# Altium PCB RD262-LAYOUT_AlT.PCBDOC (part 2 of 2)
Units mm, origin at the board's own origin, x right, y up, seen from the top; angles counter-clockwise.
Board outline 110 x 64.13 mm, 4 copper layers (TOP, Mid-Layer 1, Mid-Layer 2, BOTTOM), stack 0.711 mm thick; 50 components, 28 nets, 252 pads, 303 vias.
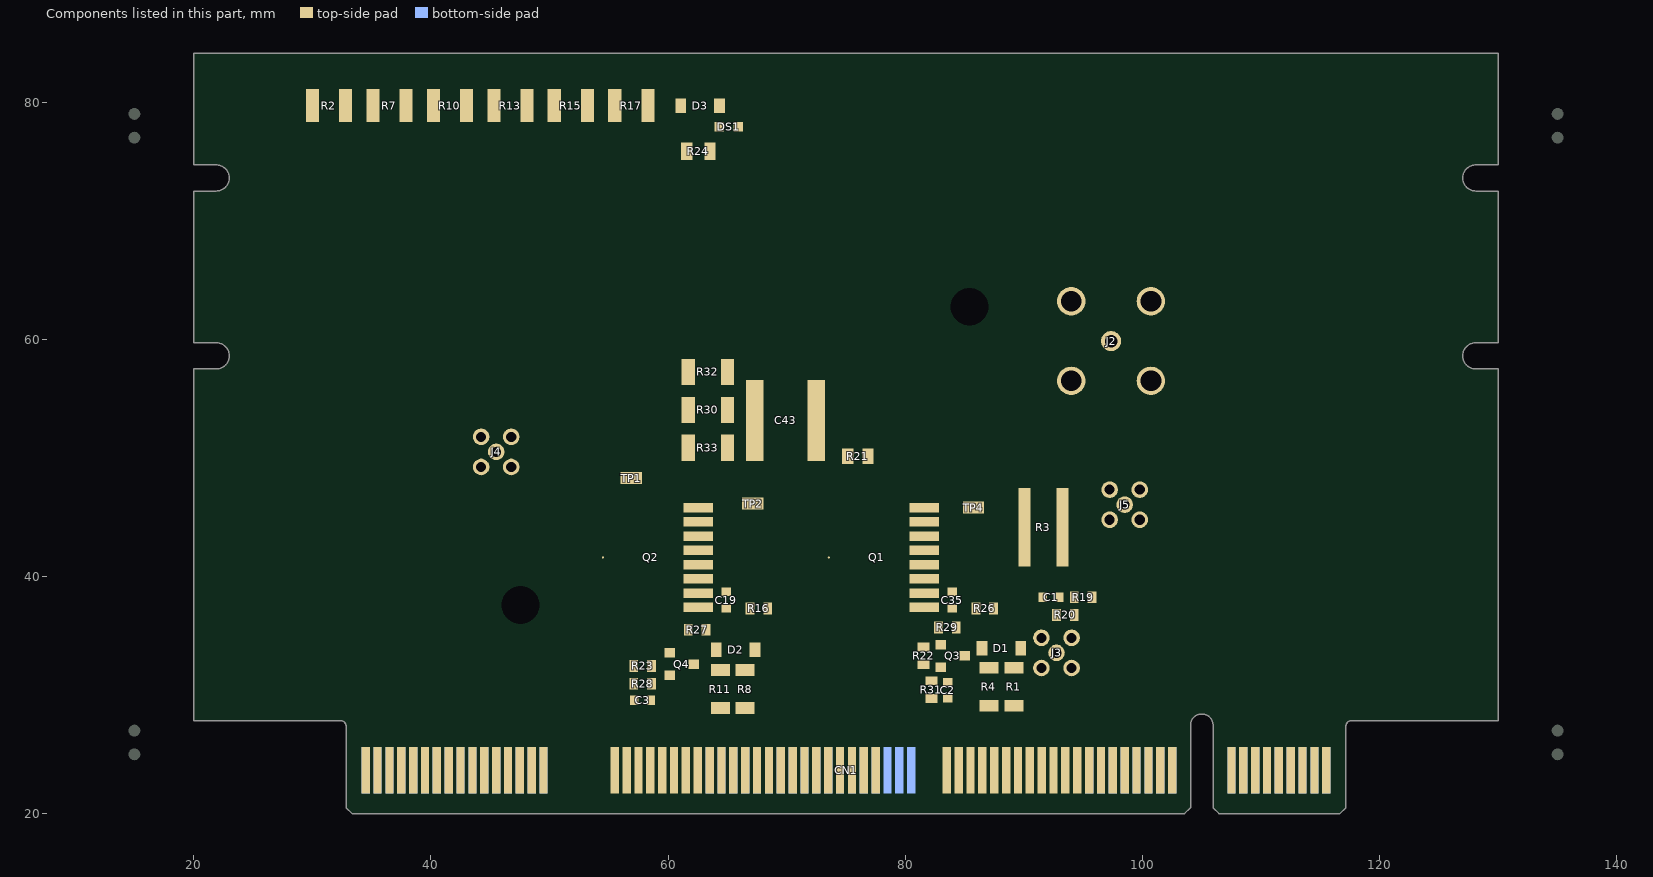
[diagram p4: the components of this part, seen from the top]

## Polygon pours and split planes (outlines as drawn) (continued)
N12552974 on Mid-Layer 2 "MID235" (solid, pour order 12): 34.2,21.7 cw(c34.2,21.75) 34.15,21.75 34.15,26 33.865,26.285 cw(c33.9,26.321) 33.85,26.321 33.85,29.35 32.85,30.35 25.521,30.35 cw(c25.521,30.4) 25.485,30.365 25.015,30.835 cw(c25.05,30.871) 25,30.871 25,81.079 cw(c25.05,81.079) 25.015,81.115 25.016,81.116 25.485,81.585 cw(c25.521,81.55) 25.521,81.6 121.529,81.6 cw(c121.529,81.55) 121.565,81.585 121.566,81.584 122.034,81.116 122.035,81.115 cw(c122,81.079) 122.05,81.079 122.05,30.871 cw(c122,30.871) 122.035,30.835 122.034,30.834 121.565,30.365 cw(c121.529,30.4) 121.529,30.35 117.15,30.35 116.15,29.35 116.15,26.321 cw(c116.1,26.321) 116.135,26.285 116.134,26.284 115.85,26 115.85,21.75 cw(c115.8,21.75) 115.8,21.7 107.2,21.7 cw(c107.2,21.75) 107.15,21.75 107.15,26 106.965,26.185 cw(c107,26.221) 106.95,26.221 106.95,27.45 ccw(c105,27.45) 103.05,27.45 103.05,26.221 cw(c103,26.221) 103.035,26.185 103.034,26.184 102.85,26 102.85,21.75 cw(c102.8,21.75) 102.8,21.7 95.2,21.7 cw(c95.2,21.75) 95.15,21.75 95.15,31.022 cw(c95.2,31.022) 95.166,31.058 ccw(c94.02,32.28) 95.695,32.28 95.695,37.4 cw(c95.745,37.4) 95.745,37.45 96.25,37.45 ccw(c96.25,38.95) 97.311,37.889 99.561,40.139 ccw(c98.5,41.2) 100,41.2 100,43.05 cw(c100.05,43.05) 100.049,43.1 ccw(c100.029,44.15) 100.771,43.407 100.772,43.408 101.142,43.778 ccw(c100.4,44.521) 101.45,44.521 101.45,47.579 ccw(c100.4,47.579) 101.142,48.322 100.772,48.692 ccw(c100.029,47.95) 100.029,49 96.971,49 ccw(c96.971,47.95) 96.228,48.692 96.15,48.615 cw(c96.115,48.65) 96.115,48.6 84.271,48.6 cw(c84.271,48.65) 84.235,48.615 83.765,49.085 cw(c83.8,49.121) 83.75,49.121 83.75,51.556 cw(c83.8,51.556) 83.766,51.592 83.808,51.634 83.809,51.634 90.225,58.05 cw(c90.26,58.015) 90.26,58.065 92.336,58.065 cw(c92.336,58.015) 92.373,57.981 ccw(c93.991,56.491) 93.951,54.292 93.952,54.292 ccw(c93.991,56.491) 95.61,57.981 cw(c95.647,58.015) 95.647,58.065 96.857,58.065 cw(c96.857,58.015) 96.87,58.063 ccw(c97.35,59.85) 96.87,61.637 cw(c96.857,61.685) 96.857,61.635 95.647,61.635 cw(c95.647,61.685) 95.61,61.719 ccw(c93.991,63.209) 93.952,65.408 93.951,65.408 ccw(c93.991,63.209) 92.373,61.719 cw(c92.336,61.685) 92.336,61.635 89.707,61.635 ccw(c89.707,59.35) 88.091,60.966 81.675,54.55 cw(c81.64,54.585) 81.64,54.535 74.707,54.535 ccw(c74.707,52.25) 73.092,53.866 73.091,53.866 71.736,52.51 71.735,52.51 71.728,52.502 ccw(c73.35,50.893) 71.065,50.893 71.065,49.5 cw(c71.015,49.5) 71.015,49.45 63.633,49.45 cw(c63.632,49.5) 63.587,49.478 ccw(c61.55,48.443) 63.166,50.059 61.609,51.616 61.599,51.625 61.599,51.626 ccw(c59.993,50) 59.993,52.285 48.4,52.285 cw(c48.4,52.335) 48.353,52.319 ccw(c46.77,51.77) 45.537,52.904 cw(c45.5,52.937) 45.463,52.904 ccw(c44.23,51.77) 43.096,50.537 cw(c43.063,50.5) 43.096,50.463 ccw(c44.23,49.23) 45.463,48.096 cw(c45.5,48.063) 45.537,48.096 ccw(c46.77,49.23) 48.353,48.681 cw(c48.4,48.665) 48.4,48.715 58.45,48.715 cw(c58.45,48.665) 58.5,48.665 58.5,36.6 cw(c58.45,36.6) 58.45,36.55 53.4,36.55 50.301,33.451 50.3,33.45 50.299,33.449 49.85,33 49.85,21.75 cw(c49.8,21.75) 49.8,21.7
0VA on Mid-Layer 2 "MID234" (solid, pour order 11): 96.971,44.1 cw(c96.971,44.15) 96.935,44.115 96.565,44.485 cw(c96.6,44.521) 96.55,44.521 96.55,47.579 cw(c96.6,47.579) 96.565,47.615 96.935,47.985 cw(c96.971,47.95) 96.971,48 100.029,48 cw(c100.029,47.95) 100.065,47.985 100.435,47.615 cw(c100.4,47.579) 100.45,47.579 100.45,44.521 cw(c100.4,44.521) 100.435,44.485 100.065,44.115 cw(c100.029,44.15) 100.029,44.1
MIDPOINT on Mid-Layer 2 "MID233" (solid, pour order 10): 63.2,21.7 cw(c63.2,21.75) 63.15,21.75 63.15,25.879 cw(c63.2,25.879) 63.165,25.915 64.385,27.135 65.235,27.985 cw(c65.271,27.95) 65.271,28 69.75,28 70.235,28.485 70.236,28.486 70.95,29.2 70.95,32.55 69.215,34.285 cw(c69.25,34.321) 69.2,34.321 69.2,38.55 68.75,39 cw(c68.785,39.036) 68.739,39.017 ccw(c67.95,38.7) 67.95,39.55 64.221,39.55 cw(c64.221,39.6) 64.185,39.565 63.865,39.885 cw(c63.9,39.921) 63.85,39.921 63.85,46.279 cw(c63.9,46.279) 63.865,46.315 64.185,46.635 cw(c64.221,46.6) 64.221,46.65 77.5,46.65 cw(c77.5,46.6) 77.55,46.6 77.55,34.425 cw(c77.5,34.425) 77.548,34.412 ccw(c80.45,33.65) 77.45,33.65 77.45,31.717 cw(c77.4,31.717) 77.445,31.694 cw(c77.4,31.717) 77.44,31.686 ccw(c80.05,29.75) 77.063,28.47 77.103,28.379 cw(c77.058,28.358) 77.107,28.367 ccw(c80.05,28.95) 77.837,26.925 cw(c77.8,26.891) 77.845,26.913 cw(c77.8,26.891) 77.85,26.891 77.85,21.75 cw(c77.8,21.75) 77.8,21.7
no net on BOTTOM "BOTTOM48" (solid, pour order 9): 131,21 131,25.936 ccw(c130.5,27.35) 131,28.764 131,56.595 ccw(c130.475,58) 131.975,58 131.975,59.2 ccw(c130.475,59.2) 131,60.605 131,71.586 ccw(c130.5,73) 132,73 132,74.2 ccw(c130.5,74.2) 131,75.614 131,83 139,83 139,21
no net on BOTTOM "BOTTOM47" (solid, pour order 8): 119.15,21 119.15,25.85 129,25.85 129,21
no net on BOTTOM "BOTTOM46" (solid, pour order 7): 21,21 21,25.85 30.85,25.85 30.85,21
no net on BOTTOM "BOTTOM45" (solid, pour order 6): 11,21 11,83 19,83 19,75.614 ccw(c19.5,74.2) 18,74.2 18,73 ccw(c19.5,73) 19,71.586 19,60.605 ccw(c19.525,59.2) 18.025,59.2 18.025,58 ccw(c19.525,58) 19,56.595 19,28.764 ccw(c19.5,27.35) 19,25.936 19,21
N12552974 on BOTTOM "BOTTOM44" (solid, pour order 5): 95.2,21.7 cw(c95.2,21.75) 95.15,21.75 95.15,28.932 cw(c95.2,28.932) 95.184,28.979 ccw(c94.02,32.28) 97.52,32.28 97.52,36.245 cw(c97.57,36.245) 97.548,36.29 ccw(c96.043,39.45) 98.518,36.975 99.814,38.272 99.815,38.272 99.816,38.273 100.474,38.931 100.475,38.932 ccw(c98,41.407) 101.254,40.118 ccw(c98,41.407) 101.5,41.407 101.5,41.708 cw(c101.55,41.708) 101.525,41.752 ccw(c99.77,44.78) 103.27,44.78 103.27,47.05 cw(c103.312,47.078) 103.262,47.081 ccw(c99.77,47.32) 98.518,50.588 cw(c98.5,50.635) 98.5,50.585 cw(c98.5,50.635) 98.482,50.588 ccw(c97.23,47.32) 95.568,50.4 cw(c95.544,50.444) 95.541,50.394 ccw(c95.35,47.15) 94.858,50.362 cw(c94.85,50.412) 94.85,50.362 cw(c94.85,50.412) 94.842,50.362 ccw(c94.35,47.15) 91.455,48.627 cw(c91.411,48.65) 91.411,48.6 86.63,48.6 cw(c86.63,48.65) 86.581,48.639 ccw(c83.65,48) 85.771,50.121 84.069,51.824 cw(c84.104,51.859) 84.069,51.894 90.189,58.014 90.189,58.015 cw(c90.225,57.98) 90.271,57.96 ccw(c93.991,56.491) 97.309,54.256 cw(c97.35,54.228) 97.392,54.256 ccw(c100.709,56.491) 102.944,59.809 cw(c102.972,59.85) 102.944,59.892 ccw(c100.709,63.209) 97.391,65.444 cw(c97.35,65.472) 97.309,65.444 ccw(c93.991,63.209) 90.285,61.704 cw(c90.239,61.685) 90.289,61.685 cw(c90.239,61.685) 90.239,61.635 89.707,61.635 ccw(c89.707,59.35) 88.091,60.966 81.675,54.55 cw(c81.64,54.585) 81.662,54.54 cw(c81.64,54.585) 81.64,54.535 74.707,54.535 ccw(c74.707,52.25) 73.528,54.207 cw(c73.502,54.25) 73.502,54.2 71.671,54.2 cw(c71.671,54.25) 71.635,54.215 71.415,54.435 cw(c71.45,54.471) 71.4,54.471 71.4,81.079 cw(c71.45,81.079) 71.415,81.115 71.885,81.585 cw(c71.921,81.55) 71.898,81.595 cw(c71.921,81.55) 71.921,81.6 121.529,81.6 cw(c121.529,81.55) 121.565,81.585 122.035,81.115 cw(c122,81.079) 122.05,81.079 122.05,71.939 cw(c122,71.939) 122.023,71.895 ccw(c123.5,69) 120.25,69 120.25,30.871 cw(c120.2,30.871) 120.235,30.835 119.765,30.365 cw(c119.729,30.4) 119.729,30.35 117.15,30.35 116.15,29.35 116.15,26.321 cw(c116.1,26.321) 116.135,26.285 115.85,26 115.85,21.75 cw(c115.8,21.75) 115.8,21.7 107.2,21.7 cw(c107.2,21.75) 107.15,21.75 107.15,26 106.965,26.185 cw(c107,26.221) 106.95,26.221 106.95,27.45 ccw(c105,27.45) 103.05,27.45 103.05,26.221 cw(c103,26.221) 103.035,26.185 102.85,26 102.85,21.75 cw(c102.8,21.75) 102.8,21.7
PGND on BOTTOM "BOTTOM43" (solid, pour order 4): 34.2,21.7 cw(c34.2,21.75) 34.15,21.75 34.15,26 33.865,26.285 cw(c33.9,26.321) 33.85,26.321 33.85,29.35 32.85,30.35 30.271,30.35 cw(c30.271,30.4) 30.235,30.365 29.765,30.835 cw(c29.8,30.871) 29.75,30.871 29.75,74 ccw(c26.5,74) 26.5,77.25 25.521,77.25 cw(c25.521,77.3) 25.485,77.265 25.015,77.735 cw(c25.05,77.771) 25,77.771 25,81.079 cw(c25.05,81.079) 25.001,81.091 cw(c25.05,81.079) 25.015,81.115 25.016,81.116 25.485,81.585 cw(c25.521,81.55) 25.507,81.598 cw(c25.521,81.55) 25.521,81.6 67.879,81.6 cw(c67.879,81.55) 67.915,81.585 68.385,81.115 cw(c68.35,81.079) 68.4,81.079 68.4,49.721 cw(c68.35,49.721) 68.385,49.685 68.165,49.465 cw(c68.129,49.5) 68.129,49.45 63.026,49.45 cw(c63.026,49.5) 62.986,49.469 ccw(c61.6,48.393) 62.841,49.634 61.234,51.241 ccw(c59.993,50) 59.993,51.755 50.32,51.755 cw(c50.32,51.805) 50.27,51.804 ccw(c46.77,51.77) 45.518,55.038 cw(c45.5,55.085) 45.5,55.035 cw(c45.5,55.085) 45.482,55.038 ccw(c44.23,51.77) 40.962,50.518 cw(c40.915,50.5) 40.965,50.5 cw(c40.915,50.5) 40.962,50.482 ccw(c44.23,49.23) 45.482,45.962 cw(c45.5,45.915) 45.5,45.965 cw(c45.5,45.915) 45.518,45.962 ccw(c46.77,49.23) 47.638,45.839 cw(c47.65,45.791) 47.65,45.841 cw(c47.65,45.791) 47.7,45.791 47.7,40.5 cw(c47.65,40.5) 47.65,40.45 47.558,40.45 47.557,40.45 ccw(c47.55,37.6) 47.494,34.751 cw(c47.493,34.701) 47.5,34.75 47.542,34.75 47.543,34.75 47.557,34.75 47.558,34.75 48.359,34.75 cw(c48.359,34.7) 48.381,34.745 cw(c48.359,34.7) 48.397,34.733 ccw(c50.55,36.6) 49.813,33.847 cw(c49.8,33.799) 49.828,33.84 cw(c49.8,33.799) 49.85,33.799 49.85,21.75 cw(c49.8,21.75) 49.8,21.7
MIDPOINT on BOTTOM "BOTTOM42" (solid, pour order 3): 63.2,21.7 cw(c63.2,21.75) 63.15,21.75 63.15,25.879 cw(c63.2,25.879) 63.165,25.915 64.385,27.135 65.235,27.985 cw(c65.271,27.95) 65.271,28 69.75,28 70.235,28.485 70.236,28.486 70.95,29.2 70.95,32.55 69.215,34.285 cw(c69.25,34.321) 69.2,34.321 69.2,38.55 68.75,39 cw(c68.785,39.036) 68.739,39.017 ccw(c67.95,38.7) 67.95,39.55 64.221,39.55 cw(c64.221,39.6) 64.185,39.565 63.865,39.885 cw(c63.9,39.921) 63.85,39.921 63.85,46.279 cw(c63.9,46.279) 63.865,46.315 64.185,46.635 cw(c64.221,46.6) 64.221,46.65 77.5,46.65 cw(c77.5,46.6) 77.55,46.6 77.55,34.425 cw(c77.5,34.425) 77.548,34.412 ccw(c80.45,33.65) 77.45,33.65 77.45,31.717 cw(c77.4,31.717) 77.44,31.687 ccw(c80.05,29.75) 80.049,26.5 80.05,26.5 80.479,26.5 cw(c80.479,26.45) 80.515,26.485 80.835,26.165 cw(c80.8,26.129) 80.85,26.129 80.85,21.75 cw(c80.8,21.75) 80.8,21.7
N12552974 on BOTTOM "BOTTOM41" (solid, pour order 2): 50.55,36.55 cw(c50.55,36.6) 50.5,36.6 50.5,46.6 cw(c50.55,46.6) 50.55,46.65 58.45,46.65 cw(c58.45,46.6) 58.5,46.6 58.5,36.6 cw(c58.45,36.6) 58.45,36.55

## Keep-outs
Keep-Out Layer:
  lines w0.1: 20,57.5 21.9,57.5 ccw(c21.9,58.6) 21.9,59.7 20,59.7 ; 20.025,57.5 19.525,57.5 cw(c19.525,58) 19.025,58 19.025,59.2 cw(c19.525,59.2) 19.525,59.7 20.025,59.7 ; 32.85,25 32.85,20.5 ; 117.15,25 117.15,20.5 ; 129.975,57.5 130.475,57.5 ccw(c130.475,58) 130.975,58 130.975,59.2 ccw(c130.475,59.2) 130.475,59.7 129.975,59.7 ; 130,57.5 128.1,57.5 cw(c128.1,58.6) 128.1,59.7 130,59.7 ; 32.85,20.5 33.35,20 ; 32.85,20.5 32.85,27.35 ccw(c32.35,27.35) 32.35,27.85 20,27.85 19.5,27.85 ccw(c19.5,27.35) 19.5,26.85 31.85,26.85 31.85,20 20,20 10,20 10,84.125 20,84.125 130,84.125 140,84.125 140,20 130,20 118.15,20 118.15,26.85 130.5,26.85 ccw(c130.5,27.35) 130.5,27.85 130,27.85 117.65,27.85 ccw(c117.65,27.35) 117.15,27.35 117.15,20.5 ; 32.85,20.5 33.35,20 ; 33.35,20 103.55,20 ; 33.35,20 103.55,20 ; 103.55,20 104.05,20.5 ; 103.55,20 104.05,20.5 ; 104.05,20.5 104.05,27.45 ; 104.05,20.5 104.05,27.45 ; 104.05,27.45 cw(c105,27.45) 105.95,27.45 ; 104.05,27.45 cw(c105,27.45) 105.95,27.45 ; 105.95,20.5 106.45,20 ; 105.95,20.5 105.95,27.45 ; 105.95,20.5 105.95,27.45 ; 105.95,20.5 106.45,20 ; 106.45,20 116.65,20 ; 106.45,20 116.65,20 ; 116.65,20 117.15,20.5 ; 116.65,20 117.15,20.5 ; 19,73 ccw(c19.5,73) 19.5,72.5 20,72.5 21.9,72.5 ccw(c21.9,73.6) 21.9,74.7 20,74.7 19.5,74.7 ccw(c19.5,74.2) 19,74.2 19,73 ; 59.322,36.256 ccw(c59.957,36.256) 60.592,36.256 60.592,47.686 ccw(c59.957,47.686) 59.322,47.686 59.322,36.256 ; 78.323,36.076 ccw(c78.958,36.076) 79.593,36.076 79.593,47.506 ccw(c78.958,47.506) 78.958,48.141 ccw(c78.958,47.506) 78.323,47.506 78.323,36.076 ; 128.1,72.5 cw(c128.1,73.6) 128.1,74.7 130,74.7 130.5,74.7 cw(c130.5,74.2) 131,74.2 131,73 cw(c130.5,73) 130.5,72.5 130,72.5 128.1,72.5

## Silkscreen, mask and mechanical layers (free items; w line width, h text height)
Top Overlay:
  lines w0.2: 64.85,32.9 64.85,34.7 ; 64.95,32.9 64.95,34.7 ; 65.1,32.9 65.1,34.7 ; 87.25,33.1 87.25,34.85 ; 87.35,33.1 87.35,34.85 ; 87.5,33.1 87.5,34.85
  text "SiC MOSFET Power Daughter Card" at 83,78 h1.27
  text "HV Present" at 67.75,77.5 h0.91
  text "TOLL Package" at 83,75 h1.27
  text "Vds Lower" at 103.1,59.5 h0.81
  text "SOURCE" at 84.75,52.75 h0.81 r270
  text "DRAIN" at 53.8,50 h0.81
  text "SOURCE" at 64.75,47.75 h0.81
  text "Vgs Lower" at 101.2,45.5 h0.81
  text "Is Lower" at 95.25,32.5 h0.81
Top Solder:
  lines w2: 15,25 15,27 ; 15,77 15,79 ; 135,25 135,27 ; 135,77 135,79
Mechanical 2:
  lines w0.1: 20,27.85 20,57.5 21.9,57.5 ccw(c21.9,58.6) 23,58.6 ccw(c21.9,58.6) 21.9,59.7 20,59.7 20,72.5 21.9,72.5 ccw(c21.9,73.6) 23,73.6 ccw(c21.9,73.6) 21.9,74.7 20,74.7 20,84.125 130,84.125 130,74.7 128.1,74.7 ccw(c128.1,73.6) 127,73.6 ccw(c128.1,73.6) 128.1,72.5 130,72.5 130,59.7 128.1,59.7 ccw(c128.1,58.6) 127,58.6 ccw(c128.1,58.6) 128.1,57.5 130,57.5 130,27.85 117.65,27.85 ccw(c117.65,27.35) 117.15,27.35 117.15,20.5 116.65,20 106.45,20 105.95,20.5 105.95,27.45 ccw(c105,27.45) 105,28.4 ccw(c105,27.45) 104.05,27.45 104.05,20.5 103.55,20 33.35,20 32.85,20.5 32.85,27.35 ccw(c32.35,27.35) 32.35,27.85 20,27.85 ; 59.322,36.256 ccw(c59.957,36.256) 60.592,36.256 60.592,47.686 ccw(c59.957,47.686) 59.322,47.686 59.322,36.256 ; 78.323,36.076 ccw(c78.958,36.076) 79.593,36.076 79.593,47.506 ccw(c78.958,47.506) 78.958,48.141 ccw(c78.958,47.506) 78.323,47.506 78.323,36.076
